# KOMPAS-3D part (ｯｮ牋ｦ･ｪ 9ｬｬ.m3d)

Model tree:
1. Эскиз:1
2. Операция выдавливания:1
     Расстояние 1 = 8
3. Эскиз:2
4. Операция выдавливания:2
     Расстояние 1 = 1
5. Эскиз:3
6. Операция выдавливания:3
     Расстояние 1 = 2.5; Угол 1 = 8
7. Эскиз:4
8. Вырезать элемент выдавливания:1
     Расстояние 1 = 20
9. Эскиз:5
10. Вырезать элемент выдавливания:2
     Расстояние 1 = 3; Угол 1 = 19
11. Скругление:1
     Радиус = 1
12. Скругление:2
     Радиус = 1
13. Скругление:3
     Радиус = 1
14. Эскиз:6
15. Эскиз:7
16. Вырезать элемент выдавливания:3
     Расстояние 2 = 30; Расстояние 1 = 60
17. Эскиз:8
18. Вырезать элемент выдавливания:4
     Расстояние 2 = 30; Расстояние 1 = 60
19. Эскиз:9
20. Операция выдавливания:4
     Расстояние 1 = 10; Расстояние 2 = 62
21. Эскиз:10
22. Вырезать элемент выдавливания:5
     Расстояние 2 = 30; Расстояние 1 = 60
23. Скругление:4
     Радиус = 2
24. Скругление:5
     Радиус = 2
25. Эскиз:11
26. Вырезать элемент выдавливания:6
     Расстояние 1 = 10
27. Эскиз:12
28. Вырезать элемент выдавливания:7
     Расстояние 1 = 2.5; Угол 1 = 3
29. Эскиз:13
30. Вырезать элемент выдавливания:8
     Расстояние 2 = 40; Расстояние 1 = 30
31. Эскиз:14
32. Операция выдавливания:5
     Расстояние 1 = 10
33. Операция выдавливания:6
     Расстояние 1 = 2.5; Расстояние 2 = 5.94316
34. Эскиз:15
35. Вырезать элемент выдавливания:9
     Расстояние 1 = 20
36. Эскиз:16
37. Вырезать элемент выдавливания:10
     Расстояние 1 = 10
38. Операция выдавливания:7
     Расстояние 1 = 2
39. Операция выдавливания:8
     Расстояние 1 = 0.4
40. Операция выдавливания:9
     Расстояние 1 = 0.4
